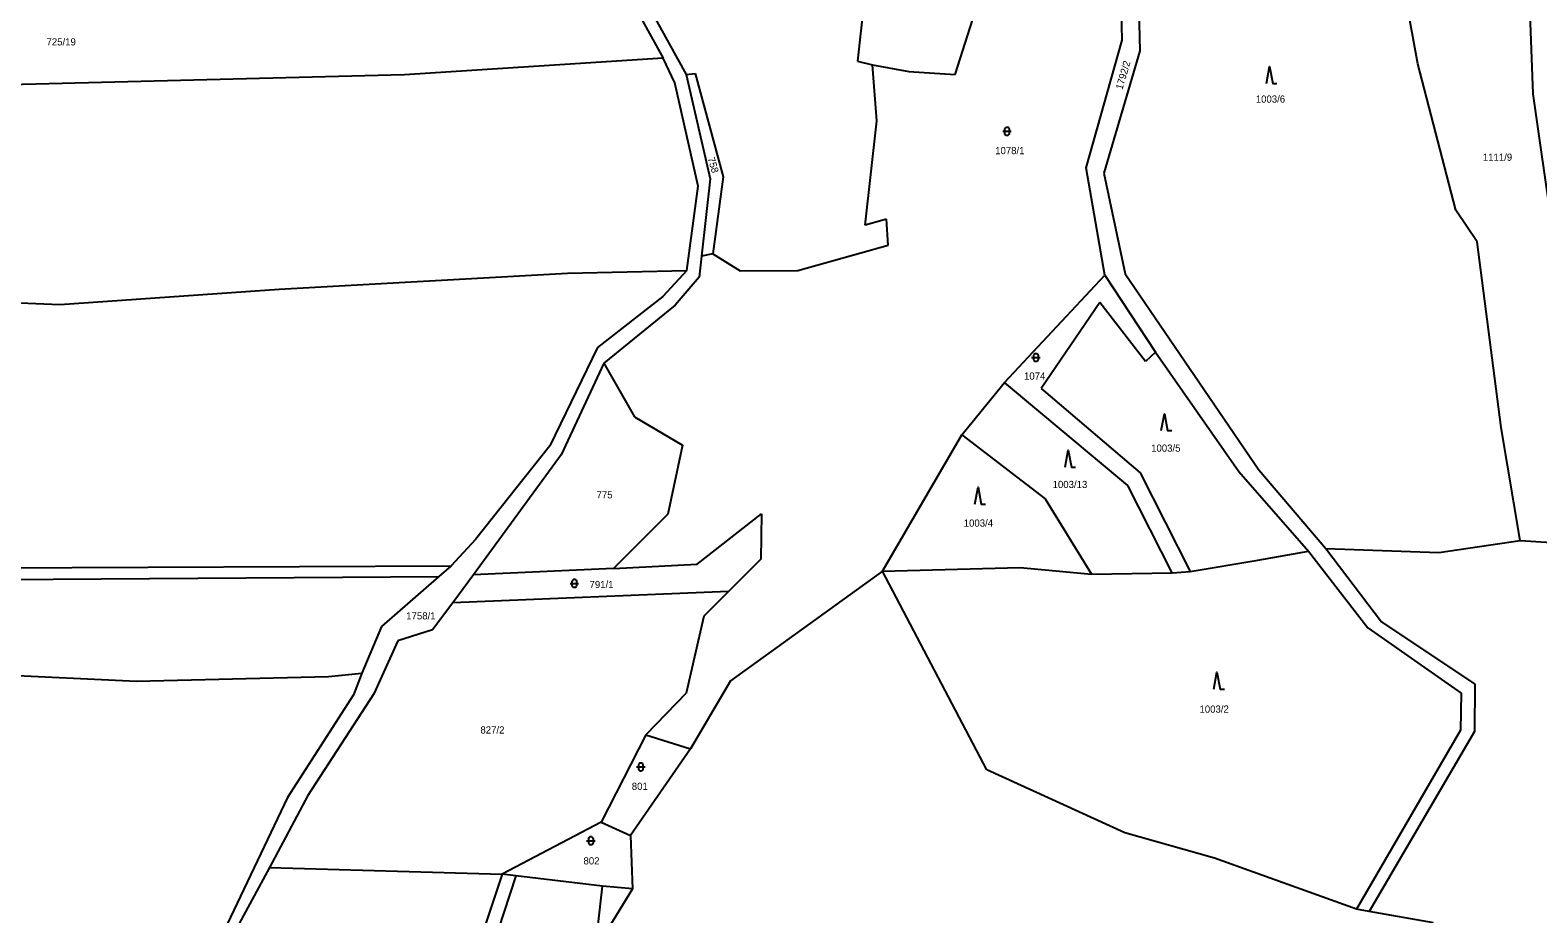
# Model space of a CAD drawing. Extents: x -799786 to -795190, y -1021716 to -1017834.
# Drawn here: x -798982.6 to -798625.3, y -1019794.2 to -1019585 of the extents above; entities that cross this region are included whole.
import ezdxf

# ---------------------------------------------------------------- set-up
doc = ezdxf.new("R2010")
doc.units = 0
for name, color, linetype in [('Default', 7, 'Continuous'), ('KN_HRANICE', 7, 'Continuous'), ('KN_KULTURY', 7, 'Continuous'), ('KN_PARCELY', 7, 'Continuous')]:
    doc.layers.add(name, color=color, linetype=linetype)

# ---------------------------------------------------------------- blocks, each defined once
blk = doc.blocks.new('308')
at = {"layer": 'Default'}
blk.add_lwpolyline([(-0.75, 0), (0, 4), (0.75, 0), (1.75, 0)], dxfattribs=at)
blk = doc.blocks.new('316')
at = {"layer": 'Default'}
for points in [[(-1, 1), (0.27, 1), (1, 1)], [(-0.5, 1.5), (-0.4, 1.79), (-0.15, 1.97), (0.16, 1.97), (0.41, 1.79), (0.51, 1.5), (0.51, 0.5), (0.41, 0.21), (0.16, 0.03), (-0.15, 0.03), (-0.4, 0.21), (-0.5, 0.5), (-0.5, 1.5)]]:
    blk.add_lwpolyline(points, dxfattribs=at)

msp = doc.modelspace()

# ---------------------------------------------------------------- linework, layer by layer
at = {"layer": 'KN_HRANICE'}
for p, q in [((-798721.17, -1019529.97), (-798719.63, -1019589.9)), ((-798763.39, -1019595.46), (-798753.06, -1019563.2)), ((-798723.85, -1019587.37), (-798724.33, -1019563.53)), ((-798841.6, -1019569.19), (-798827.09, -1019595.48)), ((-798653.74, -1019592.96), (-798658.38, -1019567.59)), ((-798843.91, -1019571.19), (-798832.55, -1019591.58)), ((-798626.43, -1019600.01), (-798627.51, -1019571.18)), ((-798784.99, -1019577.96), (-798786.52, -1019592.32)), ((-798732.38, -1019617.59), (-798723.85, -1019587.37)), ((-798832.55, -1019591.58), (-798893.88, -1019595.58)), ((-798829.83, -1019597.48), (-798832.55, -1019591.58)), ((-798719.63, -1019589.9), (-798728.17, -1019618.85)), ((-798827.09, -1019595.48), (-798824.98, -1019595.27)), ((-798824.98, -1019595.27), (-798818.35, -1019619.72)), ((-798786.52, -1019592.32), (-798782.94, -1019593.16)), ((-798781.99, -1019606.44), (-798782.94, -1019593.16)), ((-798782.94, -1019593.16), (-798774.35, -1019594.72)), ((-798774.35, -1019594.72), (-798763.39, -1019595.46)), ((-798644.79, -1019627.58), (-798653.74, -1019592.96)), ((-798893.88, -1019595.58), (-799004.28, -1019598.31)), ((-798824.25, -1019621.94), (-798829.83, -1019597.48)), ((-798827.09, -1019595.48), (-798821.4, -1019620.15)), ((-798615.11, -1019679.63), (-798626.43, -1019600.01)), ((-798784.73, -1019631.11), (-798781.99, -1019606.44)), ((-798821.4, -1019620.15), (-798823.51, -1019638.49)), ((-798818.35, -1019619.72), (-798820.77, -1019637.96)), ((-798727.97, -1019642.95), (-798732.38, -1019617.59)), ((-798728.17, -1019618.85), (-798723.13, -1019642.64)), ((-798826.98, -1019641.9), (-798824.25, -1019621.94)), ((-798779.67, -1019629.74), (-798784.73, -1019631.11)), ((-798779.25, -1019635.85), (-798779.67, -1019629.74)), ((-798639.73, -1019635.07), (-798644.79, -1019627.58)), ((-798820.77, -1019637.96), (-798823.51, -1019638.49)), ((-798820.77, -1019637.96), (-798814.34, -1019641.97)), ((-798800.64, -1019641.86), (-798779.25, -1019635.85)), ((-798634.06, -1019679.05), (-798639.73, -1019635.07)), ((-798823.51, -1019638.49), (-798824.03, -1019643.48)), ((-798923.52, -1019646.27), (-798855.24, -1019642.54)), ((-798855.24, -1019642.54), (-798826.98, -1019641.9)), ((-798826.98, -1019641.9), (-798832.67, -1019648.01)), ((-798824.03, -1019643.48), (-798829.72, -1019650.12)), ((-798814.34, -1019641.97), (-798800.64, -1019641.86)), ((-798751.67, -1019668.43), (-798727.97, -1019642.95)), ((-798727.97, -1019642.95), (-798715.96, -1019661.19)), ((-798723.13, -1019642.64), (-798691.41, -1019689.12)), ((-799030.13, -1019647.8), (-798975.55, -1019649.9)), ((-798975.55, -1019649.9), (-798923.52, -1019646.27)), ((-798832.67, -1019648.01), (-798848.16, -1019660.14)), ((-798829.72, -1019650.12), (-798846.65, -1019663.85)), ((-798729.13, -1019649.49), (-798743.03, -1019669.8)), ((-798718.28, -1019663.4), (-798729.13, -1019649.49)), ((-798848.16, -1019660.14), (-798859.44, -1019683.43)), ((-798715.96, -1019661.19), (-798718.28, -1019663.4)), ((-798715.96, -1019661.19), (-798696.15, -1019689.44)), ((-798846.65, -1019663.85), (-798856.76, -1019685.57)), ((-798846.65, -1019663.85), (-798839.38, -1019676.5)), ((-798761.79, -1019680.76), (-798751.67, -1019668.43)), ((-798722.49, -1019692.78), (-798751.67, -1019668.43)), ((-798743.03, -1019669.8), (-798719.54, -1019689.83)), ((-798839.38, -1019676.5), (-798828.03, -1019683.22)), ((-798780.64, -1019713.08), (-798761.79, -1019680.76)), ((-798761.79, -1019680.76), (-798742.09, -1019695.94)), ((-798629.51, -1019705.82), (-798634.06, -1019679.05)), ((-798859.44, -1019683.43), (-798877.02, -1019705.56)), ((-798828.03, -1019683.22), (-798831.47, -1019699.59)), ((-798856.76, -1019685.57), (-798877.54, -1019713.98)), ((-798719.54, -1019689.83), (-798707.74, -1019713.13)), ((-798696.15, -1019689.44), (-798679.66, -1019708.35)), ((-798691.41, -1019689.12), (-798675.55, -1019707.72)), ((-798711.95, -1019713.44), (-798722.49, -1019692.78)), ((-798742.09, -1019695.94), (-798731.11, -1019713.81)), ((-798831.47, -1019699.59), (-798844.33, -1019712.45)), ((-798824.52, -1019711.39), (-798809.24, -1019699.48)), ((-798809.24, -1019699.48), (-798809.45, -1019710.24)), ((-798877.02, -1019705.56), (-798882.81, -1019711.83)), ((-798648.79, -1019708.66), (-798629.51, -1019705.82)), ((-798629.51, -1019705.82), (-798602.59, -1019707.48)), ((-798691.7, -1019710.51), (-798679.66, -1019708.35)), ((-798679.66, -1019708.35), (-798665.65, -1019726.48)), ((-798675.55, -1019707.72), (-798648.79, -1019708.66)), ((-798675.55, -1019707.72), (-798662.38, -1019725.11)), ((-799012.43, -1019712.36), (-798882.81, -1019711.83)), ((-798882.81, -1019711.83), (-798885.71, -1019714.35)), ((-798844.33, -1019712.45), (-798877.54, -1019713.98)), ((-798844.33, -1019712.45), (-798824.52, -1019711.39)), ((-798809.45, -1019710.24), (-798817.09, -1019717.88)), ((-798780.64, -1019713.08), (-798816.66, -1019739.02)), ((-798780.64, -1019713.08), (-798747.97, -1019712.23)), ((-798755.87, -1019760.09), (-798780.64, -1019713.08)), ((-798747.97, -1019712.23), (-798731.11, -1019713.81)), ((-798711.95, -1019713.44), (-798707.74, -1019713.13)), ((-798707.74, -1019713.13), (-798691.7, -1019710.51)), ((-798988.55, -1019715.09), (-798885.71, -1019714.35)), ((-798885.71, -1019714.35), (-798899.3, -1019726.15)), ((-798877.54, -1019713.98), (-798882.44, -1019720.57)), ((-798731.11, -1019713.81), (-798711.95, -1019713.44)), ((-798817.09, -1019717.88), (-798882.44, -1019720.57)), ((-798817.09, -1019717.88), (-798822.94, -1019723.73)), ((-798882.44, -1019720.57), (-798887.21, -1019727.01)), ((-798822.94, -1019723.73), (-798827.15, -1019742.01)), ((-798899.3, -1019726.15), (-798903.97, -1019737.24)), ((-798887.21, -1019727.01), (-798895.43, -1019729.54)), ((-798665.65, -1019726.48), (-798643.52, -1019741.98)), ((-798662.38, -1019725.11), (-798640.25, -1019739.87)), ((-798895.43, -1019729.54), (-798901.12, -1019742.09)), ((-799016.36, -1019736.35), (-798957.39, -1019739.14)), ((-798957.39, -1019739.14), (-798911.86, -1019738.04)), ((-798911.86, -1019738.04), (-798903.97, -1019737.24)), ((-798903.97, -1019737.24), (-798905.97, -1019742.4)), ((-798816.66, -1019739.02), (-798826.13, -1019755.13)), ((-798640.25, -1019739.87), (-798640.36, -1019751.04)), ((-798905.97, -1019742.4), (-798921.54, -1019766.7)), ((-798901.12, -1019742.09), (-798916.79, -1019766.17)), ((-798827.15, -1019742.01), (-798836.67, -1019751.86)), ((-798643.52, -1019741.98), (-798643.63, -1019750.72)), ((-798836.67, -1019751.86), (-798847.3, -1019772.48)), ((-798836.67, -1019751.86), (-798826.13, -1019755.13)), ((-798643.63, -1019750.72), (-798668.27, -1019793.15)), ((-798640.36, -1019751.04), (-798665.32, -1019793.68)), ((-798826.13, -1019755.13), (-798840.35, -1019775.69)), ((-798723.16, -1019775.02), (-798755.87, -1019760.09)), ((-798921.54, -1019766.7), (-798937.42, -1019799.96)), ((-798916.79, -1019766.17), (-798925.86, -1019783.25)), ((-798847.3, -1019772.48), (-798870.69, -1019784.81)), ((-798847.3, -1019772.48), (-798840.35, -1019775.69)), ((-798840.35, -1019775.69), (-798839.82, -1019788.29)), ((-798701.98, -1019781.03), (-798723.16, -1019775.02)), ((-798925.86, -1019783.25), (-798935.63, -1019801.33)), ((-798925.86, -1019783.25), (-798870.69, -1019784.81)), ((-798668.27, -1019793.15), (-798701.98, -1019781.03)), ((-798870.69, -1019784.81), (-798882.07, -1019818.86)), ((-798867.48, -1019785.23), (-798878.91, -1019819.91)), ((-798867.48, -1019785.23), (-798870.69, -1019784.81)), ((-798846.93, -1019787.66), (-798867.48, -1019785.23)), ((-798848.35, -1019800.2), (-798846.93, -1019787.66)), ((-798839.82, -1019788.29), (-798846.93, -1019787.66)), ((-798839.82, -1019788.29), (-798862.47, -1019825.11)), ((-798665.32, -1019793.68), (-798668.27, -1019793.15)), ((-798650.08, -1019796.37), (-798665.32, -1019793.68))]:
    msp.add_line(p, q, dxfattribs=at)

# ---------------------------------------------------------------- block references
at = {"layer": 'KN_KULTURY'}
for name, p in [('308', (-798688.91, -1019597.58)), ('316', (-798751.11, -1019609.91)), ('316', (-798744.27, -1019663.48)), ('308', (-798713.83, -1019679.79)), ('308', (-798736.61, -1019688.46)), ('308', (-798757.97, -1019697.22)), ('316', (-798853.61, -1019716.98)), ('308', (-798701.37, -1019740.99)), ('316', (-798837.87, -1019760.45)), ('316', (-798849.7, -1019777.91))]:
    msp.add_blockref(name, p, dxfattribs=at)

# ---------------------------------------------------------------- texts
at = {"layer": 'KN_PARCELY'}
for s, p in [('725/19', (-798978.67, -1019588.59)), ('1003/6', (-798692.17, -1019602.13)), ('1078/1', (-798753.92, -1019614.34)), ('1111/9', (-798638.38, -1019615.9)), ('1074', (-798747.08, -1019667.72)), ('1003/5', (-798716.96, -1019684.79)), ('1003/13', (-798740.31, -1019693.4)), ('775', (-798848.36, -1019695.84)), ('1003/4', (-798761.36, -1019702.54)), ('791/1', (-798850.02, -1019717.08)), ('1758/1', (-798893.45, -1019724.51)), ('1003/2', (-798705.51, -1019746.59)), ('827/2', (-798875.87, -1019751.53)), ('801', (-798840.01, -1019764.88)), ('802', (-798851.45, -1019782.53))]:
    msp.add_text(s, height=1.7, dxfattribs=at).set_placement(p)
for s, rotation, p in [('1792/2', 73.74, (-798723.77, -1019599.18)), ('758', 286.823, (-798822.07, -1019615.32))]:
    msp.add_text(s, height=1.7, rotation=rotation, dxfattribs=at).set_placement(p)

doc.saveas('drawing.dxf')
